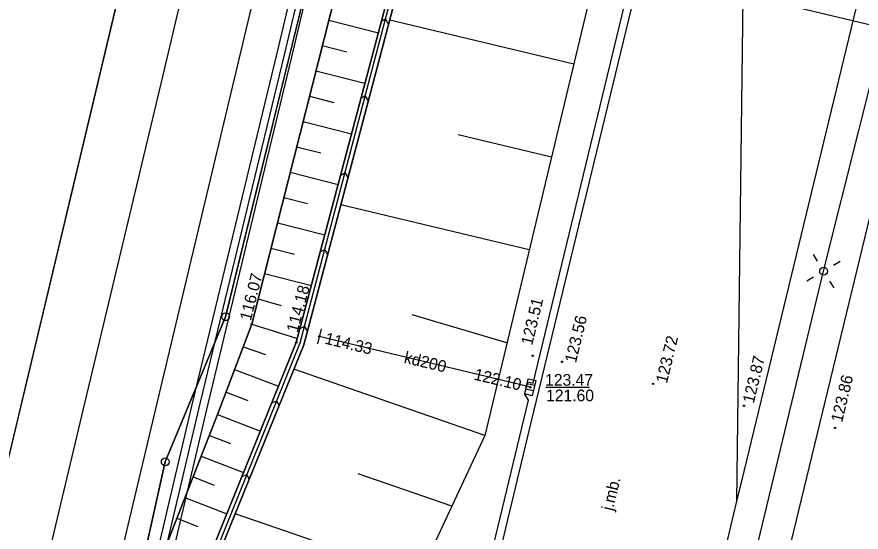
# Model space of a CAD drawing. Extents: x 6424617 to 6425697, y 5665845 to 5667190.
# Drawn here: x 6425259.4 to 6425313.5, y 5666321.5 to 5666354.6 of the extents above; entities that cross this region are included whole.
import ezdxf

# ---------------------------------------------------------------- set-up
doc = ezdxf.new("R2010")
doc.units = 0
for name, color, linetype in [('Warstwa 1', 7, 'Continuous'), ('Warstwa 10', 7, 'Continuous'), ('Warstwa 12', 7, 'Continuous'), ('Warstwa 13', 7, 'Continuous'), ('Warstwa 14', 7, 'Continuous'), ('Warstwa 15', 7, 'Continuous'), ('Warstwa 2', 7, 'Continuous'), ('Warstwa 20', 7, 'Continuous'), ('Warstwa 21', 7, 'Continuous'), ('Warstwa 25', 7, 'Continuous'), ('Warstwa 4', 7, 'Continuous'), ('Warstwa 47', 7, 'Continuous'), ('Warstwa 6', 7, 'Continuous'), ('Warstwa 61', 7, 'Continuous'), ('Warstwa 8', 7, 'Continuous'), ('Warstwa 9', 7, 'Continuous')]:
    doc.layers.add(name, color=color, linetype=linetype)

msp = doc.modelspace()

# ---------------------------------------------------------------- linework, layer by layer
at = {"layer": 'Warstwa 1'}
for p, q in [((6425272.8, 5666335.34), (6425294.11, 5666422.45)), ((6425272.8, 5666335.34), (6425294.11, 5666422.45)), ((6425244.275, 5666264.977), (6425279.037, 5666410.906)), ((6425244.275, 5666264.977), (6425279.037, 5666410.906)), ((6425268.93, 5666326.03), (6425272.8, 5666335.34)), ((6425268.93, 5666326.03), (6425272.8, 5666335.34)), ((6425252.81, 5666253.65), (6425268.93, 5666326.03)), ((6425252.81, 5666253.65), (6425268.93, 5666326.03))]:
    msp.add_line(p, q, dxfattribs=at)
at = {"layer": 'Warstwa 10'}
msp.add_lwpolyline([(6425267.728, 5666315.146), (6425271.19, 5666329.86), (6425276.57, 5666352.13), (6425283.28, 5666380.44), (6425290.28, 5666409.92), (6425300.88, 5666454.64), (6425307.494, 5666481.767)], dxfattribs=at)
for centre in [(6425272.8, 5666335.34), (6425268.93, 5666326.03)]:
    msp.add_circle(centre, 0.25, dxfattribs=at)
at = {"layer": 'Warstwa 12'}
for points in [[(6425305.48, 5666314.773), (6425311.14, 5666338.26), (6425315.72, 5666356.59), (6425314.85, 5666358.59), (6425315.59, 5666360.88), (6425316.68, 5666361.57), (6425321.81, 5666382.32), (6425327.66, 5666405.82), (6425332.54, 5666426.33), (6425338.92, 5666452.89), (6425344.68, 5666476.52), (6425348.06, 5666490.52), (6425353.32, 5666512.48), (6425356.9, 5666527.18)], [(6425375.53, 5666339.45), (6425305.977, 5666356.006)], [(6425292.33, 5666330.82), (6425292.09, 5666330.88), (6425278.8, 5666334.08)]]:
    msp.add_lwpolyline(points, dxfattribs=at)
at = {"layer": 'Warstwa 14'}
msp.add_line((6425296.13, 5666330.794), (6425293.337, 5666330.794), dxfattribs=at)
for centre in [(6425278.8, 5666334.08), (6425292.09, 5666330.88), (6425292.33, 5666330.82)]:
    msp.add_circle(centre, 0.045, dxfattribs=at)
at = {"layer": 'Warstwa 2'}
msp.add_circle((6425311.14, 5666338.26), 0.25, dxfattribs=at)
at = {"layer": 'Warstwa 20'}
for points in [[(6425306.496, 5666399.029), (6425300.821, 5666375.348), (6425289.41, 5666327.719), (6425285.185, 5666318.653), (6425284.331, 5666314.945)], [(6425292.365, 5666377.252), (6425289.64, 5666377.785), (6425288.462, 5666378.016), (6425285.098, 5666378.674), (6425284.514, 5666374.573), (6425281.056, 5666360.861), (6425274.474, 5666334.861), (6425272.279, 5666329.059), (6425269.154, 5666321.093), (6425267.61, 5666315.147)]]:
    msp.add_lwpolyline(points, dxfattribs=at)
at = {"layer": 'Warstwa 21'}
msp.add_line((6425278.918, 5666334.566), (6425278.682, 5666333.594), dxfattribs=at)
for points in [[(6425270.982, 5666315.107), (6425272.032, 5666319.27), (6425277.811, 5666333.541), (6425285.262, 5666361.705), (6425288.33, 5666373.734), (6425289.376, 5666376.843), (6425292.365, 5666377.252), (6425292.98, 5666380.282), (6425290.684, 5666381.655), (6425291.516, 5666385.64), (6425292.444, 5666389.955), (6425293.272, 5666396.442), (6425293.428, 5666397.92), (6425295.255, 5666405.439), (6425296.508, 5666407.837), (6425298.975, 5666417.006), (6425304.639, 5666439.871), (6425307.108, 5666449.766)], [(6425292.365, 5666377.252), (6425289.376, 5666376.843), (6425288.222, 5666377.14), (6425287.852, 5666373.863), (6425284.784, 5666361.834), (6425277.334, 5666333.689), (6425271.555, 5666319.419), (6425270.472, 5666315.113)]]:
    msp.add_lwpolyline(points, dxfattribs=at)
at = {"layer": 'Warstwa 25'}
for centre in [(6425274.474, 5666334.861), (6425277.334, 5666333.689), (6425292.493, 5666332.835), (6425294.377, 5666332.451), (6425300.213, 5666331.035), (6425306.04, 5666329.63), (6425311.876, 5666328.214)]:
    msp.add_circle(centre, 0.045, dxfattribs=at)
at = {"layer": 'Warstwa 4'}
for p, q in [((6425292.613, 5666330.935), (6425292.125, 5666331.046)), ((6425292.535, 5666330.594), (6425292.047, 5666330.705))]:
    msp.add_line(p, q, dxfattribs=at)
for points in [[(6425310.752, 5666338.902), (6425310.493, 5666339.329)], [(6425311.782, 5666338.648), (6425312.209, 5666338.907)], [(6425310.498, 5666337.872), (6425310.071, 5666337.613)], [(6425311.528, 5666337.618), (6425311.787, 5666337.191)]]:
    msp.add_lwpolyline(points, dxfattribs=at)
msp.add_lwpolyline([(6425292.685, 5666331.252), (6425292.463, 5666330.277), (6425291.975, 5666330.388), (6425292.197, 5666331.363)], close=True, dxfattribs=at)
at = {"layer": 'Warstwa 47'}
msp.add_lwpolyline([(6425306.496, 5666399.029), (6425300.821, 5666375.348), (6425289.41, 5666327.719), (6425285.185, 5666318.653), (6425284.331, 5666314.945)], dxfattribs=at)
at = {"layer": 'Warstwa 6'}
for points in [[(6425294.11, 5666422.45), (6425272.8, 5666335.34), (6425268.93, 5666326.03), (6425252.81, 5666253.65), (6425242.84, 5666212.49), (6425237.49, 5666195.18)], [(6425294.11, 5666422.45), (6425272.8, 5666335.34), (6425268.93, 5666326.03), (6425252.81, 5666253.65), (6425242.84, 5666212.49), (6425237.49, 5666195.18)], [(6425227.334, 5666191.99), (6425232.133, 5666212.582), (6425235.255, 5666226.065), (6425243.369, 5666261.198), (6425244.275, 5666264.977), (6425279.037, 5666410.906)], [(6425288.589, 5666314.894), (6425292.222, 5666329.989), (6425291.989, 5666330.384), (6425292.173, 5666331.171), (6425292.512, 5666331.084), (6425298.36, 5666355.247), (6425298.107, 5666355.651), (6425298.291, 5666356.438), (6425298.62, 5666356.362), (6425304.943, 5666382.487), (6425304.691, 5666382.892), (6425304.875, 5666383.678), (6425304.875, 5666383.678), (6425305.204, 5666383.602), (6425306.368, 5666388.415)]]:
    msp.add_lwpolyline(points, dxfattribs=at)
msp.add_lwpolyline([(6425217.631, 5666278.959), (6425217.156, 5666267.745), (6425221.085, 5666266.797), (6425231.986, 5666266.785), (6425236.914, 5666266.626), (6425244.275, 5666264.977), (6425279.037, 5666410.906), (6425251.855, 5666415.084)], close=True, dxfattribs=at)
at = {"layer": 'Warstwa 61'}
msp.add_lwpolyline([(6425267.728, 5666315.146), (6425267.754, 5666315.255), (6425271.19, 5666329.86), (6425276.57, 5666352.13), (6425283.28, 5666380.44), (6425290.28, 5666409.92), (6425300.88, 5666454.64), (6425306.981, 5666479.664), (6425307.494, 5666481.768)], dxfattribs=at)
at = {"layer": 'Warstwa 8'}
for p, q in [((6425306.044, 5666325.418), (6425357.544, 5666538.388)), ((6425309.895, 5666324.328), (6425361.428, 5666537.448)), ((6425292.396, 5666328.566), (6425306.342, 5666386.207)), ((6425305.585, 5666323.515), (6425306.342, 5666386.207)), ((6425305.585, 5666323.515), (6425306.342, 5666386.207)), ((6425268.791, 5666350.829), (6425273.889, 5666372.234)), ((6425268.54, 5666330.327), (6425274.559, 5666355.627)), ((6425265.554, 5666337.213), (6425268.791, 5666350.829)), ((6425263.693, 5666329.424), (6425265.554, 5666337.213)), ((6425264.928, 5666315.18), (6425268.54, 5666330.327)), ((6425260.318, 5666315.235), (6425263.693, 5666329.424)), ((6425289.104, 5666314.888), (6425292.396, 5666328.566)), ((6425305.585, 5666323.515), (6425306.044, 5666325.418)), ((6425307.571, 5666314.665), (6425309.895, 5666324.328)), ((6425303.465, 5666314.714), (6425305.585, 5666323.515))]:
    msp.add_line(p, q, dxfattribs=at)
for points in [[(6425307.521, 5666483.989), (6425300.394, 5666454.757), (6425289.794, 5666410.035), (6425282.794, 5666380.555), (6425276.084, 5666352.246), (6425270.704, 5666329.976), (6425267.215, 5666315.152)], [(6425268.241, 5666315.14), (6425271.676, 5666329.744), (6425277.056, 5666352.014), (6425283.766, 5666380.325), (6425290.766, 5666409.805), (6425301.366, 5666454.523), (6425307.467, 5666479.546)], [(6425375.53, 5666339.45), (6425305.977, 5666356.006)]]:
    msp.add_lwpolyline(points, dxfattribs=at)
at = {"layer": 'Warstwa 9'}
for p, q in [((6425277.578, 5666333.658), (6425286.256, 5666366.621)), ((6425279.41, 5666354.361), (6425282.593, 5666353.556)), ((6425282.791, 5666354.305), (6425283.054, 5666354.458)), ((6425283.254, 5666354.115), (6425283.054, 5666354.458)), ((6425295.116, 5666351.534), (6425283.319, 5666354.361)), ((6425278.999, 5666352.736), (6425280.582, 5666352.336)), ((6425278.588, 5666351.111), (6425281.735, 5666350.315)), ((6425278.176, 5666349.486), (6425279.741, 5666349.09)), ((6425281.484, 5666349.368), (6425281.755, 5666349.526)), ((6425281.951, 5666349.19), (6425281.755, 5666349.526)), ((6425277.765, 5666347.861), (6425280.877, 5666347.074)), ((6425293.69, 5666345.58), (6425287.721, 5666347.01)), ((6425277.353, 5666346.236), (6425278.901, 5666345.845)), ((6425276.942, 5666344.611), (6425280.019, 5666343.833)), ((6425280.177, 5666344.431), (6425280.457, 5666344.594)), ((6425280.648, 5666344.265), (6425280.457, 5666344.594)), ((6425276.531, 5666342.986), (6425278.06, 5666342.599)), ((6425292.263, 5666339.626), (6425280.186, 5666342.52)), ((6425276.12, 5666341.361), (6425279.161, 5666340.591)), ((6425275.708, 5666339.736), (6425277.22, 5666339.353)), ((6425278.871, 5666339.494), (6425279.158, 5666339.661)), ((6425279.345, 5666339.341), (6425279.158, 5666339.661)), ((6425275.297, 5666338.111), (6425278.303, 5666337.351)), ((6425274.886, 5666336.486), (6425276.368, 5666336.066)), ((6425290.836, 5666333.672), (6425284.76, 5666335.462)), ((6425274.474, 5666334.861), (6425277.4, 5666333.939)), ((6425277.564, 5666334.557), (6425277.86, 5666334.729)), ((6425278.042, 5666334.416), (6425277.86, 5666334.729)), ((6425271.812, 5666319.378), (6425277.578, 5666333.658)), ((6425273.925, 5666333.41), (6425275.363, 5666332.913)), ((6425273.376, 5666331.96), (6425276.201, 5666330.892)), ((6425289.41, 5666327.719), (6425277.181, 5666331.984)), ((6425272.828, 5666330.51), (6425274.221, 5666329.977)), ((6425275.768, 5666329.822), (6425276.083, 5666329.956)), ((6425276.224, 5666329.623), (6425276.083, 5666329.956)), ((6425272.279, 5666329.059), (6425275.029, 5666327.998)), ((6425271.758, 5666327.732), (6425273.124, 5666327.2)), ((6425271.237, 5666326.404), (6425273.952, 5666325.339)), ((6425270.716, 5666325.076), (6425272.067, 5666324.546)), ((6425273.851, 5666325.089), (6425274.173, 5666325.226)), ((6425274.312, 5666324.9), (6425274.173, 5666325.226)), ((6425287.298, 5666323.186), (6425281.299, 5666325.264)), ((6425270.196, 5666323.748), (6425272.882, 5666322.695)), ((6425269.675, 5666322.42), (6425271.014, 5666321.88)), ((6425285.185, 5666318.653), (6425273.42, 5666322.698))]:
    msp.add_line(p, q, dxfattribs=at)
for points in [[(6425306.496, 5666399.029), (6425300.821, 5666375.348), (6425289.41, 5666327.719), (6425285.185, 5666318.653), (6425284.331, 5666314.945), (6425270.982, 5666315.107), (6425272.032, 5666319.27), (6425277.811, 5666333.541), (6425285.262, 5666361.705), (6425288.33, 5666373.734), (6425289.376, 5666376.843), (6425292.365, 5666377.252), (6425292.98, 5666380.282), (6425290.684, 5666381.655), (6425291.516, 5666385.64), (6425292.444, 5666389.955), (6425293.272, 5666396.442), (6425293.428, 5666397.92), (6425295.255, 5666405.439), (6425296.508, 5666407.837), (6425298.975, 5666417.006), (6425304.639, 5666439.871), (6425307.108, 5666449.766)], [(6425285.098, 5666378.674), (6425288.462, 5666378.016), (6425289.64, 5666377.785), (6425292.365, 5666377.252), (6425289.376, 5666376.843), (6425288.222, 5666377.14), (6425287.852, 5666373.863), (6425284.784, 5666361.834), (6425277.334, 5666333.689), (6425271.555, 5666319.419), (6425270.472, 5666315.113), (6425267.61, 5666315.147), (6425269.154, 5666321.093), (6425272.279, 5666329.059), (6425274.474, 5666334.861), (6425281.056, 5666360.861), (6425284.514, 5666374.573)], [(6425270.472, 5666315.113), (6425271.555, 5666319.419), (6425277.334, 5666333.689), (6425284.784, 5666361.834), (6425287.852, 5666373.863), (6425288.222, 5666377.14), (6425289.376, 5666376.843), (6425288.33, 5666373.734), (6425285.262, 5666361.705), (6425277.811, 5666333.541), (6425272.032, 5666319.27), (6425270.982, 5666315.107)]]:
    msp.add_lwpolyline(points, close=True, dxfattribs=at)

# ---------------------------------------------------------------- texts
at = {"layer": 'Warstwa 13'}
msp.add_text('kd200', height=0.75, rotation=346.4618, dxfattribs=at).set_placement((6425284.192, 5666332.396))
at = {"layer": 'Warstwa 14'}
for s, p in [('114.33', (6425279.112, 5666333.619)), ('122.10', (6425288.676, 5666331.316))]:
    msp.add_text(s, height=0.75, rotation=346.4618, dxfattribs=at).set_placement(p)
msp.add_text('121.60', height=0.75, dxfattribs=at).set_placement((6425293.352, 5666329.918))
at = {"layer": 'Warstwa 15'}
msp.add_text('123.47', height=0.75, dxfattribs=at).set_placement((6425293.289, 5666330.918))
at = {"layer": 'Warstwa 25'}
for s, rotation, p in [('116.07', 75.7966, (6425274.416, 5666335.041)), ('114.18', 75.1721, (6425277.414, 5666334.281)), ('123.51', 76.3925, (6425292.454, 5666333.465)), ('123.56', 76.3982, (6425295.262, 5666332.336)), ('123.72', 76.3982, (6425301.096, 5666331.031)), ('123.87', 76.4039, (6425306.664, 5666329.744)), ('123.86', 76.4097, (6425312.325, 5666328.518))]:
    msp.add_text(s, height=0.75, rotation=rotation, dxfattribs=at).set_placement(p)
at = {"layer": 'Warstwa 8'}
msp.add_text('j.mb.', height=0.75, rotation=76.4555, dxfattribs=at).set_placement((6425297.623, 5666322.852))

doc.saveas('drawing.dxf')
